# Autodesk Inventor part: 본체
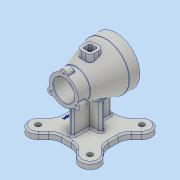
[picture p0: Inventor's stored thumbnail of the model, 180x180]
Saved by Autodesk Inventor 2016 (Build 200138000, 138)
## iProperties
Created: 2018-03
Part Number: 본체
Material: 알루미늄 6061
Document SubType Name: Modeling
Designer: 605-15
Density: 2.7 g/cm^3
Appearance: 알루미늄 - 평지
Mass: 1043.48 g
Surface Area: 885.729 cm^2
Volume: 386.474 cm^3
Author: 605-15
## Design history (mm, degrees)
sketch "스케치1"
  geometry: L1 (0, 0)-(-45, 0); L2 (-45, 0)-(-45, 20); L3 (0, 0)-(0, 100); L4 (0, 100)-(-27.5, 100); L5 (-27.5, 100)-(-27.5, 77); L6 (-27.5, 77)-(-45, 20); L7 (0, 0)-(0, -41.292)
  constraints: 14 end point, 3 perpendicular, 2 vertical, 1 horizontal
  dimensions: "d0" = 45 distance of L1.start L1.end; "d1" = 20 distance of L1.end L2.end; "d3" = 100 distance of L1.start L3.end; "d4" = 27.5 distance of L3.end L4.end; "d5" = 23 distance of L4.end L5.end
revolve "회전1" sketch "스케치1" stored, may be unused: angle "d6" = 90 deg
sketch "스케치2" dims "d7" = 55
  geometry: L1 (0, 0)-(0, 66.107); C1 r 7 at (0, 27.5); 1 further point
  constraints: 2 end point, 1 centre point, 1 coincident, 1 point on line, 1 vertical, 1 vertical alignment, 2 other
  dimensions: "d8" = 7 radius of C1
extrude "돌출1" join sketch "스케치2" distance "d9" = 15; taper "d10" = 0 deg
sketch "스케치3"
  geometry: A1 r 27.5 centre (0, -27.5) between (26.516, -34.792) and (6.943, -0.891) reference; A2 r 7 centre (0, 0) between (6.943, -0.891) and (-6.943, -0.891) reference; A3 r 27.5 centre (0, -27.5) between (-6.943, -0.891) and (-26.516, -34.792) reference; A4 r 7 centre (-23.816, -41.25) between (-26.516, -34.792) and (-19.573, -46.817) reference; A5 r 27.5 centre (0, -27.5) between (-19.573, -46.817) and (19.573, -46.817) reference; A6 r 7 centre (23.816, -41.25) between (19.573, -46.817) and (26.516, -34.792) reference; 4 further points
  constraints: 3 coincident
hole "구멍1" sketch "스케치3" at (0, 0), (23.816, -41.25), (-23.816, -41.25) diameter "d14" = 3.242; stored, may be unused: countersink angle "d18" = 90 deg, drill point angle "d20" = 118 deg; dims "d15" = 9, "d16" = 4, "d17" = 2, "d19" = 11
sketch "스케치4"
  geometry: C1 r 35 at (0, 0); 1 further point
  constraints: 1 centre point, 1 coincident
  dimensions: "d21" = 70 diameter of C1
extrude "돌출2" cut sketch "스케치4" distance "d22" = 23; taper "d23" = 0 deg
sketch "스케치5"
  geometry: C1 r 26 at (0, 0); 1 further point
  constraints: 1 centre point, 1 coincident
  dimensions: "d24" = 52 diameter of C1
extrude "돌출3" cut sketch "스케치5" distance "d25" = 47; taper "d26" = 0 deg
sketch "스케치6"
  geometry: C1 r 20 at (0, 0); 1 further point
  constraints: 1 centre point, 1 coincident
  dimensions: "d27" = 40 diameter of C1
extrude "돌출4" cut sketch "스케치6" stored distance "d28" = 47; taper "d29" = 0 deg
sketch "스케치7" dims "d30" = 80
  geometry: L1 (0, 0)-(0, -68.967); 2 further points
  constraints: 2 end point, 1 coincident, 1 point on line, 1 vertical, 1 vertical alignment, 2 other
hole "구멍2" sketch "스케치7" at (0, -40) diameter "d31" = 3.242; stored, may be unused: countersink angle "d35" = 90 deg, drill point angle "d37" = 118 deg; dims "d32" = 9, "d33" = 4, "d34" = 2, "d36" = 11
node "작업 평면1"
sketch "스케치8"
  geometry: L1 (45, 20)-(-45, 20) reference; L2 (45, 0)-(-45, 0) reference; L3 (12.5, 37.5)-(-12.5, 37.5); L4 (-12.5, 37.5)-(-12.5, 62.5); L5 (-12.5, 62.5)-(12.5, 62.5); L6 (12.5, 62.5)-(12.5, 37.5); L7 (12.5, 50)-(65.887, 50); L8 (7.5, 42.5)-(-7.5, 42.5); L9 (-7.5, 42.5)-(-7.5, 57.5); L10 (-7.5, 57.5)-(7.5, 57.5); L11 (7.5, 57.5)-(7.5, 42.5); 6 further points
  constraints: 18 end point, 6 midpoint, 4 parallel, 3 horizontal, 2 perpendicular, 2 vertical alignment, 1 horizontal alignment
  dimensions: "d42" = 25 distance of L5.end L3.start; "d43" = 25 distance of L4.end L5.end; "d44" = 50 distance between parallel lines of L7 L2; "d45" = 15 distance of L10.end L8.start; "d46" = 15 distance of L8.start L8.end
  node "투영된 루프2"
extrude "돌출5" join sketch "스케치8" stored distance "d47" = 47; taper "d48" = 0 deg
extrude "돌출6" cut sketch "스케치8" stored distance "d49" = 47; taper "d50" = 0 deg
node "작업 평면2"
sketch "스케치9"
  geometry: L1 (45, 20)-(-45, 20) reference; L2 (45, 0)-(-45, 0) reference; L3 (0, 50)-(-72.752, -22.752); L4 (0, 50)-(0, -81.55); L5 (45, 5)-(-45, 95); L6 (-45, 5)-(45, 95); L7 (9.189, 5)-(-9.189, 5); L8 (-45, 40.811)-(-45, 59.189); L9 (-9.189, 95)-(9.189, 95); L10 (45, 5)-(-45, 95); L11 (-45, 5)-(45, 95); L12 (-62.225, 13.23)-(-52.322, 23.134); L13 (-36.77, -12.225)-(-24.544, 0); L14 (36.77, -12.225)-(26.866, -2.322); L15 (62.225, 13.23)-(50, 25.456); L16 (62.225, 86.77)-(52.322, 76.866); L17 (36.77, 112.225)-(24.544, 100); L18 (-36.77, 112.225)-(-26.866, 102.322); L19 (-62.225, 86.77)-(-50, 74.544); L20 (45, 59.189)-(45, 40.811); C1 r 70 at (0, 50); A1 r 25 centre (-9.189, -20) between (-9.189, 5) and (-26.866, -2.322); A2 r 25 centre (-70, 40.811) between (-52.322, 23.134) and (-45, 40.811); A3 r 18 centre (-49.497, 0.503) between (-60.483, 14.761) and (-35.239, -10.483); A4 r 18 centre (49.497, 0.503) between (35.239, -10.483) and (60.483, 14.761); A5 r 25 centre (9.189, -20) between (26.866, -2.322) and (9.189, 5); A6 r 25 centre (70, 40.811) between (45, 40.811) and (52.322, 23.134); A7 r 18 centre (49.497, 99.497) between (60.483, 85.239) and (35.239, 110.483); A8 r 25 centre (70, 59.189) between (52.322, 76.866) and (45, 59.189); A9 r 25 centre (9.189, 120) between (9.189, 95) and (26.866, 102.322); A10 r 18 centre (-49.497, 99.497) between (-35.239, 110.483) and (-60.483, 85.239); A11 r 25 centre (-9.189, 120) between (-26.866, 102.322) and (-9.189, 95); A12 r 25 centre (-70, 59.189) between (-45, 59.189) and (-52.322, 76.866); 2 further points
  constraints: 37 end point, 32 point on circle, 13 centre point, 8 tangent, 6 point on line, 5 midpoint, 2 parallel, 2 perpendicular, 2 vertical alignment, 1 coincident, 1 equal radius, 1 horizontal, 1 vertical, 69 other
  dimensions: "d53" = 50 distance from line of L2 L3.start; "d54" = 45 deg angle of L4 L3; "d63" = 90 distance of L11.start L10.end; "d64" = 90 distance of L10.start L11.start; "d68" = 140 diameter of C1; "d71" = 360 deg dimension on C1.centre A3.centre (derived); "d73" = 25 radius of A8; "d74" = 18 radius of A7; "d75" = 45 deg angle of L1 L11; "d76" = 45 deg angle of L1 L6; "d77" = 45 deg angle of L1 L10; "d78" = 75 distance between parallel lines of L1 L9; "d79" = 66.76955 distance from line of L16.start L1; "d80" = 65.23874 distance from line of A7.start L1; "d81" = 5.23874 distance from line of A4.end L1; "d82" = 75 distance from line of L11.end L1; "d83" = 75 distance from line of L6.end L1; "d84" = 15 distance from line of L10.start L1; "d85" = 15 distance from line of L5.start L1; "d86" = 101.54986 distance from line of L4.end L1; "d87" = 75 distance from line of L5.end L1; "d88" = 15 distance from line of L6.start L1; "d89" = 42.75198 distance from line of L3.end L1
extrude "돌출7" join sketch "스케치9" distance "d90" = 12; taper "d91" = 0 deg
sketch "스케치10"
  geometry: L1 (36.77, -12.225)-(26.866, -2.322) reference; L2 (9.189, 5)-(-9.189, 5) reference; L3 (-26.866, -2.322)-(-36.77, -12.225) reference; L4 (-62.225, 13.23)-(-52.322, 23.134) reference; L5 (-45, 40.811)-(-45, 59.189) reference; L6 (-52.322, 76.866)-(-62.225, 86.77) reference; L7 (-36.77, 112.225)-(-26.866, 102.322) reference; L8 (-9.189, 95)-(9.189, 95) reference; L9 (26.866, 102.322)-(36.77, 112.225) reference; L10 (62.225, 86.77)-(52.322, 76.866) reference; L11 (45, 59.189)-(45, 40.811) reference; L12 (52.322, 23.134)-(62.225, 13.23) reference; L13 (-45, 50)-(45, 50); L14 (-4, 13)-(4, 13); L15 (4, 87)-(-4, 87); L16 (-4, 13)-(4, 87); L17 (4, 13)-(-4, 87); L18 (-24, 54)-(-24, 46); L19 (24, 46)-(24, 54); L20 (-24, 54)-(24, 46); L21 (-24, 46)-(-4, 46); L22 (24, 54)-(0, 50); L23 (-4, 49.333)-(-24, 46); L24 (-4, 87)-(-4, 54); L25 (24, 54)-(4, 54); L26 (-4, 54)-(-24, 54); L27 (4, 46)-(24, 46); L28 (4, 13)-(4, 46); L29 (4, 54)-(4, 87); L30 (-4, 46)-(-4, 13); A1 r 25 centre (9.189, -20) between (26.866, -2.322) and (9.189, 5) reference; A2 r 25 centre (-9.189, -20) between (-9.189, 5) and (-26.866, -2.322) reference; A3 r 18 centre (-49.497, 0.503) between (-62.225, 13.23) and (-36.77, -12.225) reference; A4 r 25 centre (-70, 40.811) between (-52.322, 23.134) and (-45, 40.811) reference; A5 r 25 centre (-70, 59.189) between (-45, 59.189) and (-52.322, 76.866) reference; A6 r 18 centre (-49.497, 99.497) between (-36.77, 112.225) and (-62.225, 86.77) reference; A7 r 25 centre (-9.189, 120) between (-26.866, 102.322) and (-9.189, 95) reference; A8 r 25 centre (9.189, 120) between (9.189, 95) and (26.866, 102.322) reference; A9 r 18 centre (49.497, 99.497) between (62.225, 86.77) and (36.77, 112.225) reference; A10 r 25 centre (70, 59.189) between (52.322, 76.866) and (45, 59.189) reference; A11 r 25 centre (70, 40.811) between (45, 40.811) and (52.322, 23.134) reference; A12 r 18 centre (49.497, 0.503) between (36.77, -12.225) and (62.225, 13.23) reference; 1 further point
  constraints: 36 end point, 10 parallel, 6 midpoint, 4 perpendicular, 3 horizontal
  dimensions: "d92" = 8 distance of L15.start L15.end; "d93" = 74 distance of L15.end L14.start; "d94" = 8 distance of L18.start L18.end; "d95" = 48 distance of L19.end L18.start; "d96" = 144.462 deg angle of L10 L22; "d97" = 125.538 deg angle of L10 L20; "d98" = 51.1702 deg angle of L10 L17; "d99" = 38.8298 deg angle of L10 L16; "d100" = 144.462 deg angle of L10 L23; "d101" = 49 distance between parallel lines of L2 L25; "d102" = 20.35702 distance from line of L23.start L10
extrude "돌출8" join sketch "스케치10" stored distance "d103" = 12; taper "d104" = 0 deg
sketch "스케치11"
  geometry: L1 (36.77, -12.225)-(26.866, -2.322) reference; L2 (9.189, 5)-(-9.189, 5) reference; L3 (-26.866, -2.322)-(-36.77, -12.225) reference; L4 (-62.225, 13.23)-(-52.322, 23.134) reference; L5 (-45, 40.811)-(-45, 59.189) reference; L6 (-52.322, 76.866)-(-62.225, 86.77) reference; L7 (-36.77, 112.225)-(-26.866, 102.322) reference; L8 (-9.189, 95)-(9.189, 95) reference; L9 (26.866, 102.322)-(36.77, 112.225) reference; L10 (62.225, 86.77)-(52.322, 76.866) reference; L11 (45, 59.189)-(45, 40.811) reference; L12 (52.322, 23.134)-(62.225, 13.23) reference; L13 (9.189, 5)-(-9.189, 5) reference; L14 (-9.189, 95)-(9.189, 95) reference; A1 r 25 centre (9.189, -20) between (26.866, -2.322) and (9.189, 5) reference; A2 r 25 centre (-9.189, -20) between (-9.189, 5) and (-26.866, -2.322) reference; A3 r 18 centre (-49.497, 0.503) between (-62.225, 13.23) and (-36.77, -12.225) reference; A4 r 25 centre (-70, 40.811) between (-52.322, 23.134) and (-45, 40.811) reference; A5 r 25 centre (-70, 59.189) between (-45, 59.189) and (-52.322, 76.866) reference; A6 r 18 centre (-49.497, 99.497) between (-36.77, 112.225) and (-62.225, 86.77) reference; A7 r 25 centre (-9.189, 120) between (-26.866, 102.322) and (-9.189, 95) reference; A8 r 25 centre (9.189, 120) between (9.189, 95) and (26.866, 102.322) reference; A9 r 18 centre (49.497, 99.497) between (62.225, 86.77) and (36.77, 112.225) reference; A10 r 25 centre (70, 59.189) between (52.322, 76.866) and (45, 59.189) reference; A11 r 25 centre (70, 40.811) between (45, 40.811) and (52.322, 23.134) reference; A12 r 18 centre (49.497, 0.503) between (36.77, -12.225) and (62.225, 13.23) reference; 5 further points
  constraints: 4 coincident
hole "구멍3" sketch "스케치11" at (49.497, 0.503), (-49.497, 0.503), (-49.497, 99.497), (49.497, 99.497) diameter "d106" = 10; stored, may be unused: countersink angle "d110" = 90 deg, drill point angle "d112" = 118 deg; dims "d107" = 9, "d108" = 4, "d109" = 2, "d111" = 10
sketch "스케치12"
  geometry: L1 (33, 48.85)-(33, 51.15); L2 (33, 51.15)-(37, 51.15); L3 (37, 51.15)-(37, 48.85); L4 (37, 48.85)-(33, 48.85); L5 (36.77, -12.225)-(26.866, -2.322) reference; L6 (9.189, 5)-(-9.189, 5) reference; L7 (-26.866, -2.322)-(-36.77, -12.225) reference; L8 (-62.225, 13.23)-(-52.322, 23.134) reference; L9 (-45, 40.811)-(-45, 59.189) reference; L10 (-52.322, 76.866)-(-62.225, 86.77) reference; L11 (-36.77, 112.225)-(-26.866, 102.322) reference; L12 (-9.189, 95)-(9.189, 95) reference; L13 (26.866, 102.322)-(36.77, 112.225) reference; L14 (62.225, 86.77)-(52.322, 76.866) reference; L15 (45, 59.189)-(45, 40.811) reference; L16 (52.322, 23.134)-(62.225, 13.23) reference; C1 r 5 at (-49.497, 99.497) reference; C2 r 5 at (49.497, 0.503) reference; C3 r 5 at (-49.497, 0.503) reference; C4 r 5 at (49.497, 99.497) reference; A1 r 25 centre (9.189, -20) between (26.866, -2.322) and (9.189, 5) reference; A2 r 25 centre (-9.189, -20) between (-9.189, 5) and (-26.866, -2.322) reference; A3 r 18 centre (-49.497, 0.503) between (-62.225, 13.23) and (-36.77, -12.225) reference; A4 r 25 centre (-70, 40.811) between (-52.322, 23.134) and (-45, 40.811) reference; A5 r 25 centre (-70, 59.189) between (-45, 59.189) and (-52.322, 76.866) reference; A6 r 18 centre (-49.497, 99.497) between (-36.77, 112.225) and (-62.225, 86.77) reference; A7 r 25 centre (-9.189, 120) between (-26.866, 102.322) and (-9.189, 95) reference; A8 r 25 centre (9.189, 120) between (9.189, 95) and (26.866, 102.322) reference; A9 r 18 centre (49.497, 99.497) between (62.225, 86.77) and (36.77, 112.225) reference; A10 r 25 centre (70, 59.189) between (52.322, 76.866) and (45, 59.189) reference; A11 r 25 centre (70, 40.811) between (45, 40.811) and (52.322, 23.134) reference; A12 r 18 centre (49.497, 0.503) between (36.77, -12.225) and (62.225, 13.23) reference; 3 further points
  constraints: 2 midpoint, 1 horizontal alignment, 2 other
  dimensions: "d113" = 4 distance of L1.end L2.end; "d114" = 33 horizontal distance of L1.start point (0, 0)
feature "엠보싱1" sketch "스케치12" dims "d115" = 0.5, "d116" = 0
fillet "모깎기1" dims "d117" = 3
fillet "모깎기2" dims "d118" = 1
fillet "모깎기3" dims "d122" = 8
fillet "모깎기4" dims "d123" = 3
fillet "모깎기5" dims "d124" = 3
fillet "모깎기7" dims "d126" = 3
fillet "모깎기8" dims "d127" = 3
fillet "모깎기11" dims "d130" = 3
fillet "모깎기12" dims "d131" = 3
chamfer "모따기1" distance "d132" = 1; stored, may be unused: second distance "d133" = 2, angle "d134" = 45 deg
chamfer "모따기2" distance "d135" = 3; stored, may be unused: second distance "d136" = 2, angle "d137" = 45 deg
fillet "모깎기13" dims "d138" = 1
fillet "모깎기14" dims "d139" = 3
fillet "모깎기15" dims "d140" = 3
fillet "모깎기16" dims "d141" = 3
node "솔리드1"
pattern_circular "원형 패턴1" dims angle "d12" = 360 deg
pattern_circular "원형 패턴2" dims angle "d39" = 360 deg
pattern_circular "원형 패턴3" dims angle "d120" = 360 deg
node "투영된 루프1"
node "투영된 루프3"
node "투영된 루프4"
node "투영된 루프5"
node "투영된 루프6"
other parameters: "d41" = -45, "d51" = 82, "d55" = 18, "d58" = 25, "d60" = 22.41058, "d62" = 25, "d65" = 36, "d66" = 25, "d67" = 25
